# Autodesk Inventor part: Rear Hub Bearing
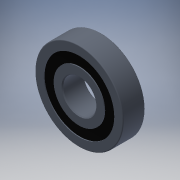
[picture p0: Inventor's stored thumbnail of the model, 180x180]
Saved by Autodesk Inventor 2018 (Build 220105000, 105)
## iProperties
Shininess: 50.0
Compacted: True
Length Units: 11272
Angle Units: 11279
Time Units: 11290
Mass Units: 11286
Length Display Precision: 4
Angle Display Precision: 2
Company: Autodesk
Created: 2000-05
Part Number: Rear Hub Bearing
Project: Inventor Samples
User Status: IN PROGRESS
Document SubType Name: Modeling
Designer: Autodesk, Inc.
Density: 8.08 g/cm^3
Material: Stainless Steel
Mass: 2.70813 g
Surface Area: 3.99293 cm^2
Volume: 0.335165 cm^3
Appearance: Dark Grey
Density: 0.0
Volumn: 0.0
Area: 0.0
PropertySet Name: Model Information
Control State: 0
Master: False
Checked Out: False
Author: Autodesk, Inc.
Revision Number: A
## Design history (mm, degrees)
node "Extrusion1" dims "d5" = 3.175, "d6" = 0
  sketch "Sketch2"
    geometry: C1 r 2.381 at (10.478, 10.795); C2 r 6.35 at (10.478, 10.795); C3 r 5.08 at (10.478, 10.795); C4 r 3.651 at (10.478, 10.795)
    constraints: 4 centre point, 2 coincident, 1 concentric, 1 other
    dimensions: "d1" = 12.7 diameter of C2; "d2" = 1.27 radial gap between concentric circles of C2 C3; "d4" = 1.27 radial gap between concentric circles of C1 C4; "d15" = 4.7625 diameter of C1
workplane "Work Plane1"
node "Fillet1" dims "d12" = 0.127
node "Chamfer1" dims "d13" = 0.127, "d14" = 0.127, "d18" = 45 deg
node "Extrusion2" dims "d16" = 2.921 (computed from d5), "d17" = 0
  sketch "Sketch4"
    geometry: C1 r 5.08 at (0, 0) reference; C2 r 3.651 at (0, 0) reference
body "Solid1"
other parameters: "d7" = -1.5875 (= -0.5 x d5)
